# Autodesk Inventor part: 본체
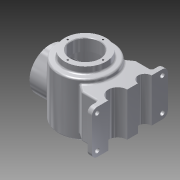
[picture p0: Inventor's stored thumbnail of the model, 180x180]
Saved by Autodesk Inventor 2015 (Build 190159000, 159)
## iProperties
Created: 2018-08
Part Number: 본체
Material: 알루미늄 6061
Document SubType Name: Modeling
Designer: line
Density: 2.7 g/cm^3
Appearance: 알루미늄 - 평지
Mass: 1879.13 g
Surface Area: 1087.48 cm^2
Volume: 695.975 cm^3
Author: line
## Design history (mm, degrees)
sketch "스케치2"
  geometry: L1 (0, 54)-(50, 54); L2 (0, 54)-(0, -54); L3 (0, 54)-(50, 54); L4 (0, 54)-(0, -54); L5 (50, -42.671)-(50, 54); A1 r 116 centre (0, 62) between (0, -54) and (50, -42.671); 1 further point
  constraints: 10 end point, 2 point on circle, 1 centre point, 1 collinear, 1 horizontal
  dimensions: "d14" = 108 vertical distance of L2.end L1.end; "d16" = 50 distance of L1.start L1.end; "d17" = 116 radius of A1; "d18" = 108 distance of L1.start L2.end; "d19" = 50 horizontal distance of L5.start A1.centre; "d20" = 62 distance of point (0, 0) A1.centre; "d21" = 8 vertical distance of L1.end A1.centre; "d119" = 42.67091 vertical distance of point (0, 0) L5.start
revolve "회전1" sketch "스케치2" stored, may be unused: angle "d22" = 90 deg
sketch "스케치3"
  geometry: C1 r 38 at (0, 0); 1 further point
  constraints: 1 centre point, 1 coincident
  dimensions: "d23" = 76 diameter of C1
extrude "돌출1" join sketch "스케치3" distance "d24" = 12; taper "d25" = 0 deg
sketch "스케치4"
  geometry: C1 r 27 at (0, 0); 1 further point
  constraints: 1 centre point, 1 coincident
  dimensions: "d26" = 54 diameter of C1
extrude "돌출2" cut sketch "스케치4" distance "d27" = 22; taper "d28" = 0 deg
sketch "스케치5" dims "d29" = 65
  geometry: 3 further points
  constraints: 2 vertical alignment, 1 coincident, 2 other
hole "구멍1" sketch "스케치5" at (0, 32.5) diameter "d30" = 3.242; stored, may be unused: countersink angle "d34" = 90 deg, drill point angle "d36" = 118 deg; dims "d31" = 8, "d32" = 4, "d33" = 2, "d35" = 10
sketch "스케치6"
  geometry: L1 (0, 66)-(0, -63.544); L2 (0, 44)-(40, 44); L3 (40, 44)-(40, -36.163); L4 (0, 44)-(40, 44); L5 (40, -36.163)-(40, 44); L6 (-27, 44)-(27, 44) reference; L7 (0, 44)-(0, -44); A1 r 106 centre (0, 62) between (0, -44) and (40, -36.163); 1 further point
  constraints: 12 end point, 2 perpendicular, 2 point on circle, 1 centre point, 1 collinear, 1 point on line, 1 vertical
  dimensions: "d41" = 40 distance of L2.start L2.end; "d42" = 106 radius of A1; "d43" = 80.16313 distance of L2.end L3.end; "d44" = 129.54354 distance of L1.start L1.end; "d45" = 18 distance of L2.start A1.centre; "d46" = 44 distance of L7.end point (0, 0); "d47" = 63.54354 distance of L1.end point (0, 0); "d48" = 40 horizontal distance of A1.centre L2.end
revolve "회전2" sketch "스케치6" stored, may be unused: angle "d49" = 90 deg
node "작업 평면1"
sketch "스케치7"
  geometry: L1 (-1.621, 66)-(1.621, 66) reference; L2 (0, 66)-(0, 4); C1 r 38 at (0, 4); 1 further point
  constraints: 2 end point, 1 centre point, 1 coincident, 1 midpoint, 1 vertical
  dimensions: "d51" = 62 distance of L2.start L2.end; "d52" = 76 diameter of C1
extrude "돌출3" join sketch "스케치7" stored distance "d53" = 22; taper "d54" = 0 deg
sketch "스케치8"
  geometry: C1 r 38 at (0, 0) reference; C2 r 27 at (0, 0); 1 further point
  constraints: 1 centre point, 1 coincident
  dimensions: "d55" = 54 diameter of C2
extrude "돌출4" cut sketch "스케치8" stored distance "d56" = 22; taper "d57" = 0 deg
sketch "스케치9" dims "d58" = 65
  geometry: C1 r 38 at (0, 0) reference; 3 further points
  constraints: 2 vertical alignment, 1 coincident, 2 other
hole "구멍2" sketch "스케치9" at (0, -32.5) diameter "d59" = 3.242; stored, may be unused: countersink angle "d63" = 90 deg, drill point angle "d65" = 118 deg; dims "d60" = 8, "d61" = 4, "d62" = 2, "d64" = 10
chamfer "모따기1" distance "d69" = 1; stored, may be unused: second distance "d70" = 2, angle "d71" = 45 deg
node "작업 평면2"
sketch "스케치11"
  geometry: L1 (0, 0)-(82, 0); L2 (82, 0)-(82, -70); L3 (82, -70)-(72, -70); L4 (72, -70)-(72, -50); L5 (72, -50)-(43.437, -50); L6 (43.437, -50)-(27.371, -38.751); L7 (82, 0)-(82, 70); L8 (82, 70)-(72, 70); L9 (72, 70)-(72, 50); L10 (72, 50)-(43.437, 50); L11 (43.437, 50)-(27.371, 38.751); C1 r 50 at (0, 0) reference; A1 r 47.442 centre (0, 0) between (27.371, -38.751) and (27.371, 38.751); 1 further point
  constraints: 22 end point, 6 perpendicular, 2 point on circle, 2 vertical, 1 centre point, 1 coincident, 1 horizontal
  dimensions: "d86" = 82 distance of L1.start L1.end; "d88" = 70 distance of L1.end L2.end; "d89" = 10 distance of L2.end L3.end; "d90" = 20 distance of L3.end L4.end; "d91" = 35 deg angle of L3 L6; "d92" = 70 distance of L1.end L7.end; "d93" = 10 distance of L7.end L8.end; "d94" = 20 distance of L8.end L9.end; "d95" = 35 deg angle of L11 L8; "d96" = 47.44242 radius of A1; "d97" = 16.0659 horizontal distance of L10.end L11.end; "d98" = 16.0659 horizontal distance of L5.end L6.end
extrude "돌출5" join sketch "스케치11" distance "d99" = 80; taper "d100" = 0 deg
sketch "스케치12"
  geometry: L1 (82, 70)-(82, -70) reference; L2 (82, 70)-(82, -70) reference; C1 r 17.5 at (82, -22.5); C2 r 12.5 at (82, 27.5); 4 further points
  constraints: 2 centre point, 2 coincident, 2 point on line, 2 vertical alignment, 1 midpoint
  dimensions: "d101" = 22.5 distance of point (82, 0) point (82, -22.5); "d102" = 27.5 distance of point (82, 27.5) point (82, 0); "d103" = 35 diameter of C1; "d104" = 25 diameter of C2
extrude "돌출6" cut sketch "스케치12" stored distance "d105" = 80; taper "d106" = 0 deg
fillet "모깎기1" dims "d107" = 3
fillet "모깎기2" dims "d108" = 10
fillet "모깎기3" dims "d109" = 3
sketch "스케치13"
  geometry: C1 r 4 at (10, -20); C2 r 4 at (70, -20); C3 r 4 at (10, 100); C4 r 4 at (70, 100); A1 r 10 centre (10, -20) between (0, -20) and (10, -30) reference; A2 r 10 centre (70, -20) between (70, -30) and (80, -20) reference; A3 r 10 centre (70, 100) between (80, 100) and (70, 110) reference; A4 r 10 centre (10, 100) between (10, 110) and (0, 100) reference; 1 further point
  constraints: 4 centre point, 4 coincident
  dimensions: "d110" = 8 diameter of C1; "d111" = 8 diameter of C2; "d112" = 8 diameter of C3; "d113" = 8 diameter of C4
extrude "돌출7" cut sketch "스케치13" distance "d114" = 20; taper "d115" = 0 deg
node "작업 평면3"
sketch "스케치14"
  geometry: C1 r 32.5 at (0, 0); 1 further point
  constraints: 1 centre point, 1 coincident, 1 other
  dimensions: "d116" = 65 diameter of C1
feature "엠보싱1" sketch "스케치14" dims "d14" = 108, "d16" = 50, "d17" = 116, "d18" = 108, "d19" = 50, "d20" = 62, "d21" = 8, "d117" = 0.5, "d118" = 0, "d119" = 42.67091
node "솔리드1"
pattern_circular "원형 패턴1" dims angle "d38" = 360 deg
pattern_circular "원형 패턴2" dims angle "d67" = 360 deg
other parameters: "d4" = 116, "d13" = 116, "d50" = -65, "d85" = -8
